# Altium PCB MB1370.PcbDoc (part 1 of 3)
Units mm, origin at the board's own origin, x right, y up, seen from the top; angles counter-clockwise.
Board outline 166 x 117 mm, 4 copper layers (Top Layer, Signal Layer 1, Signal Layer 2, Bottom Layer), stack 1.614 mm thick; 79 components, 100 nets, 342 pads, 822 vias.
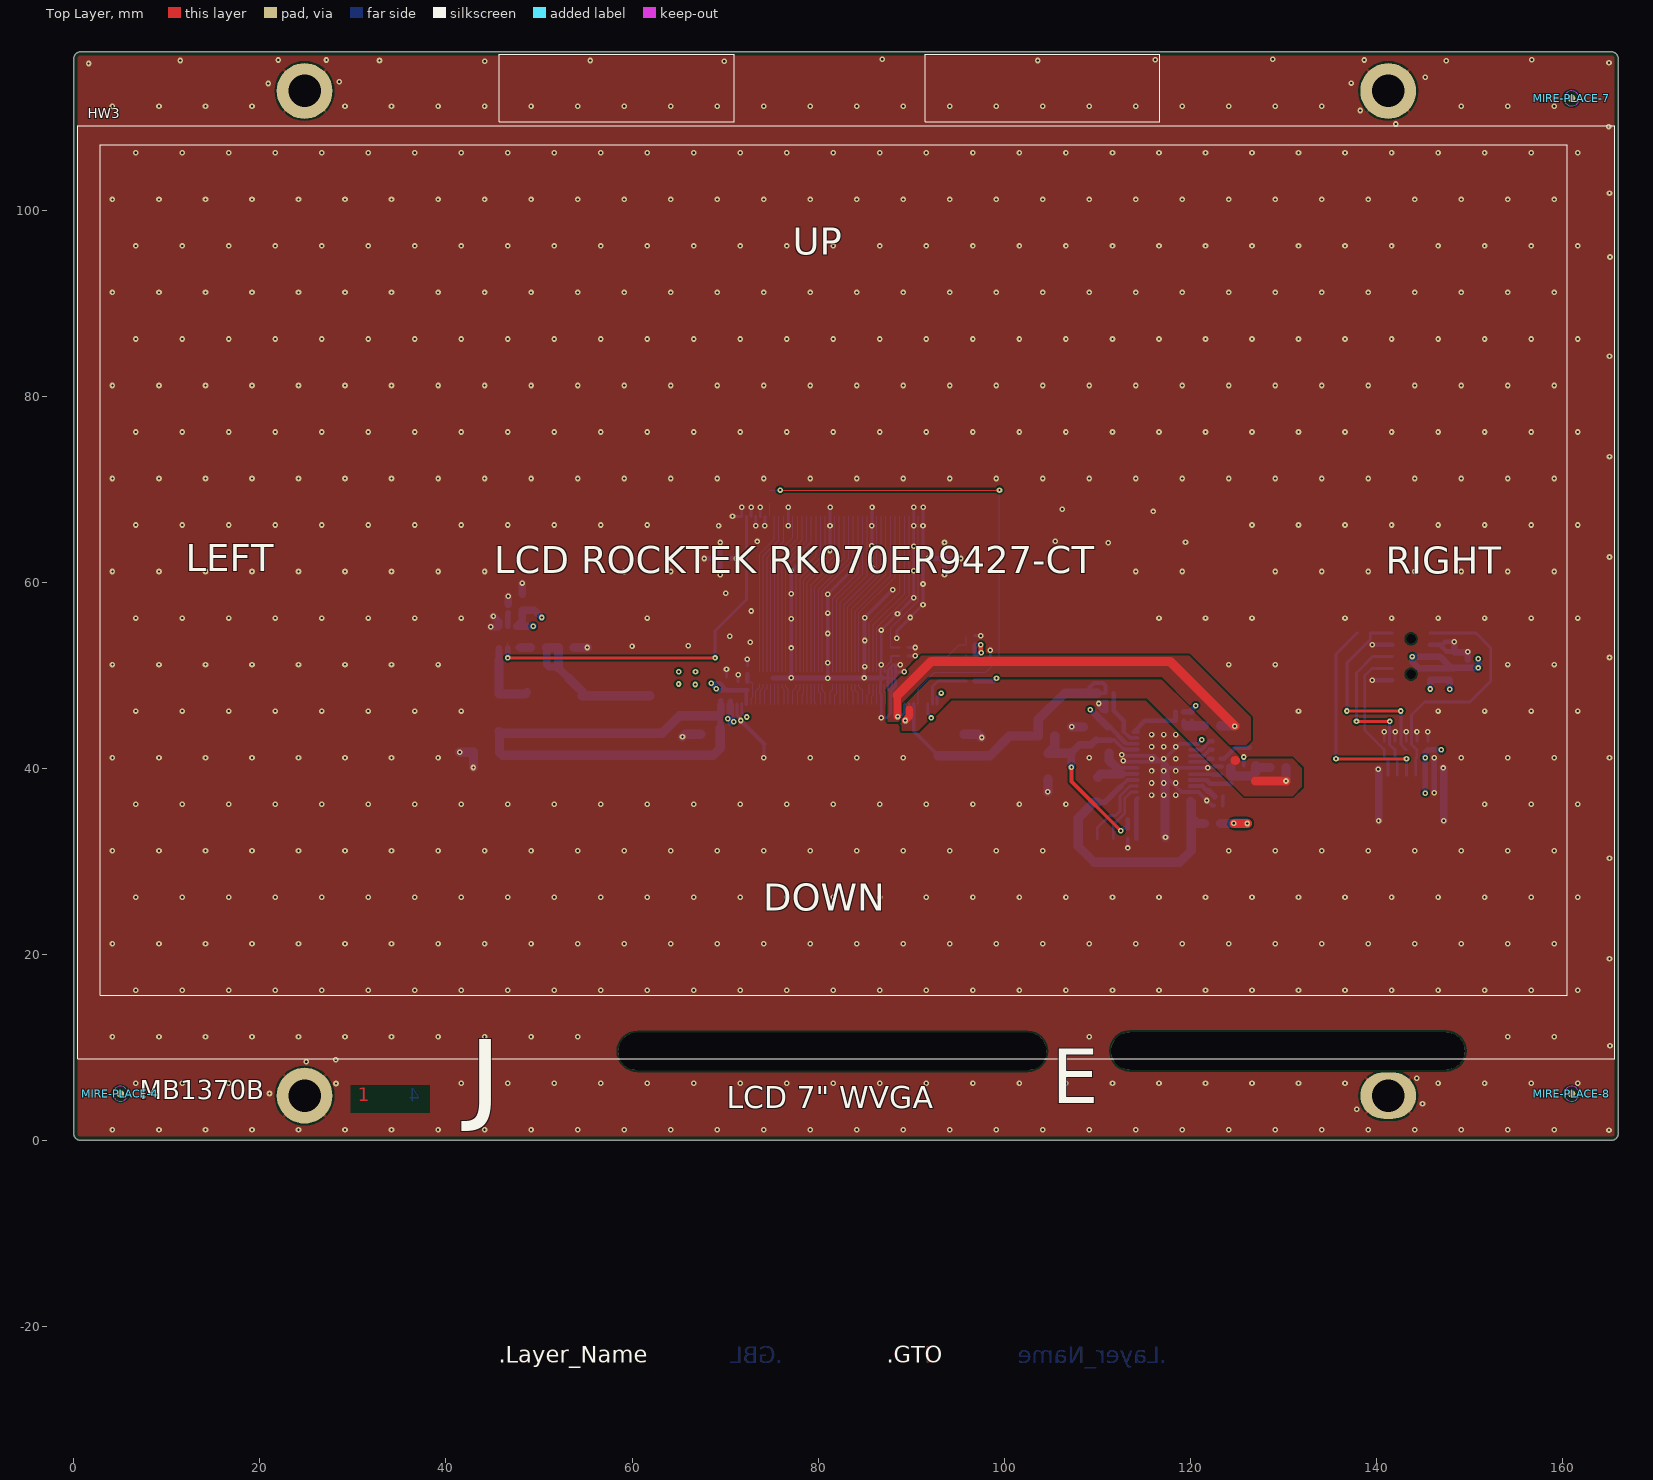
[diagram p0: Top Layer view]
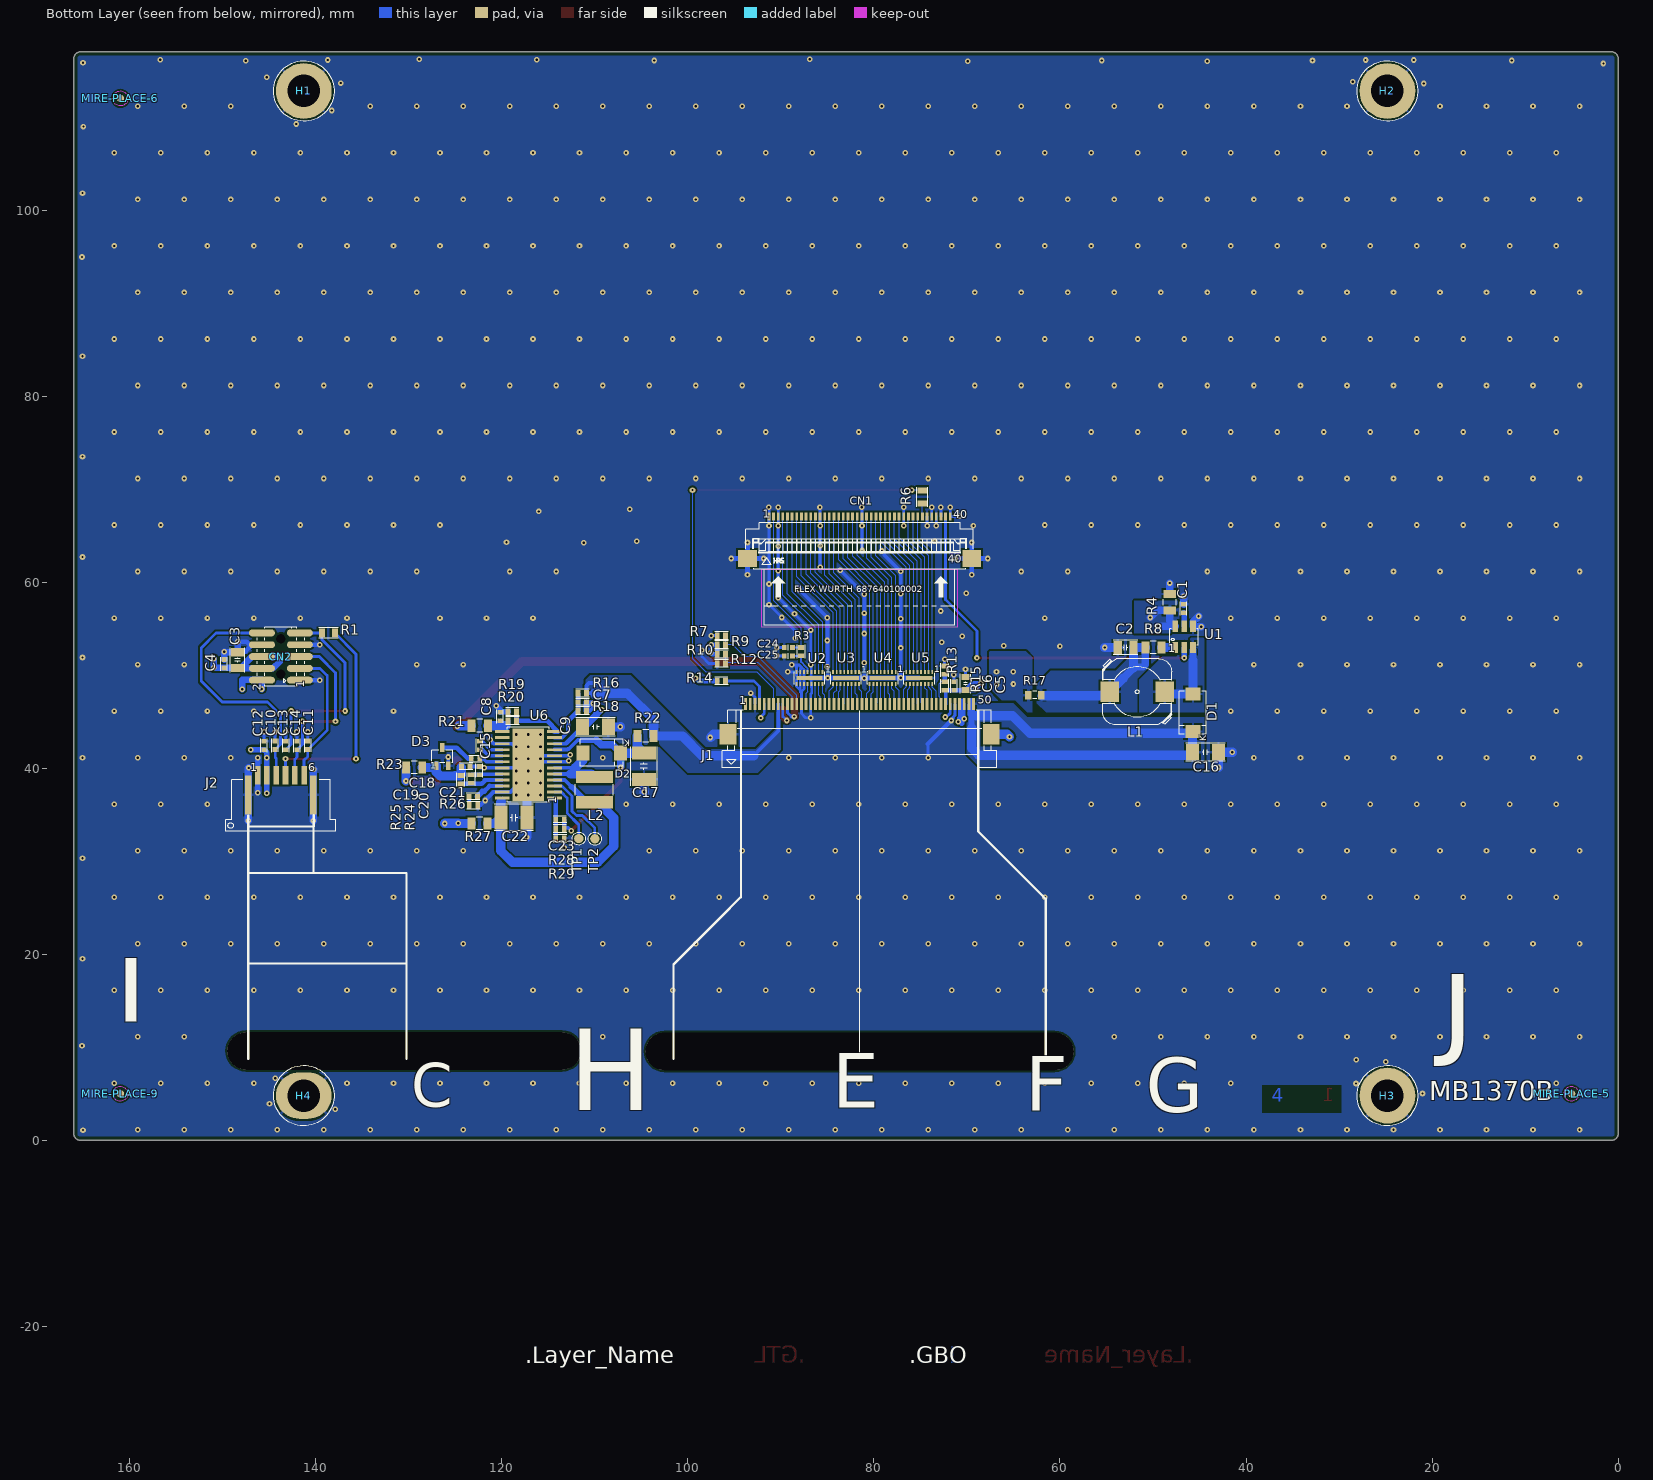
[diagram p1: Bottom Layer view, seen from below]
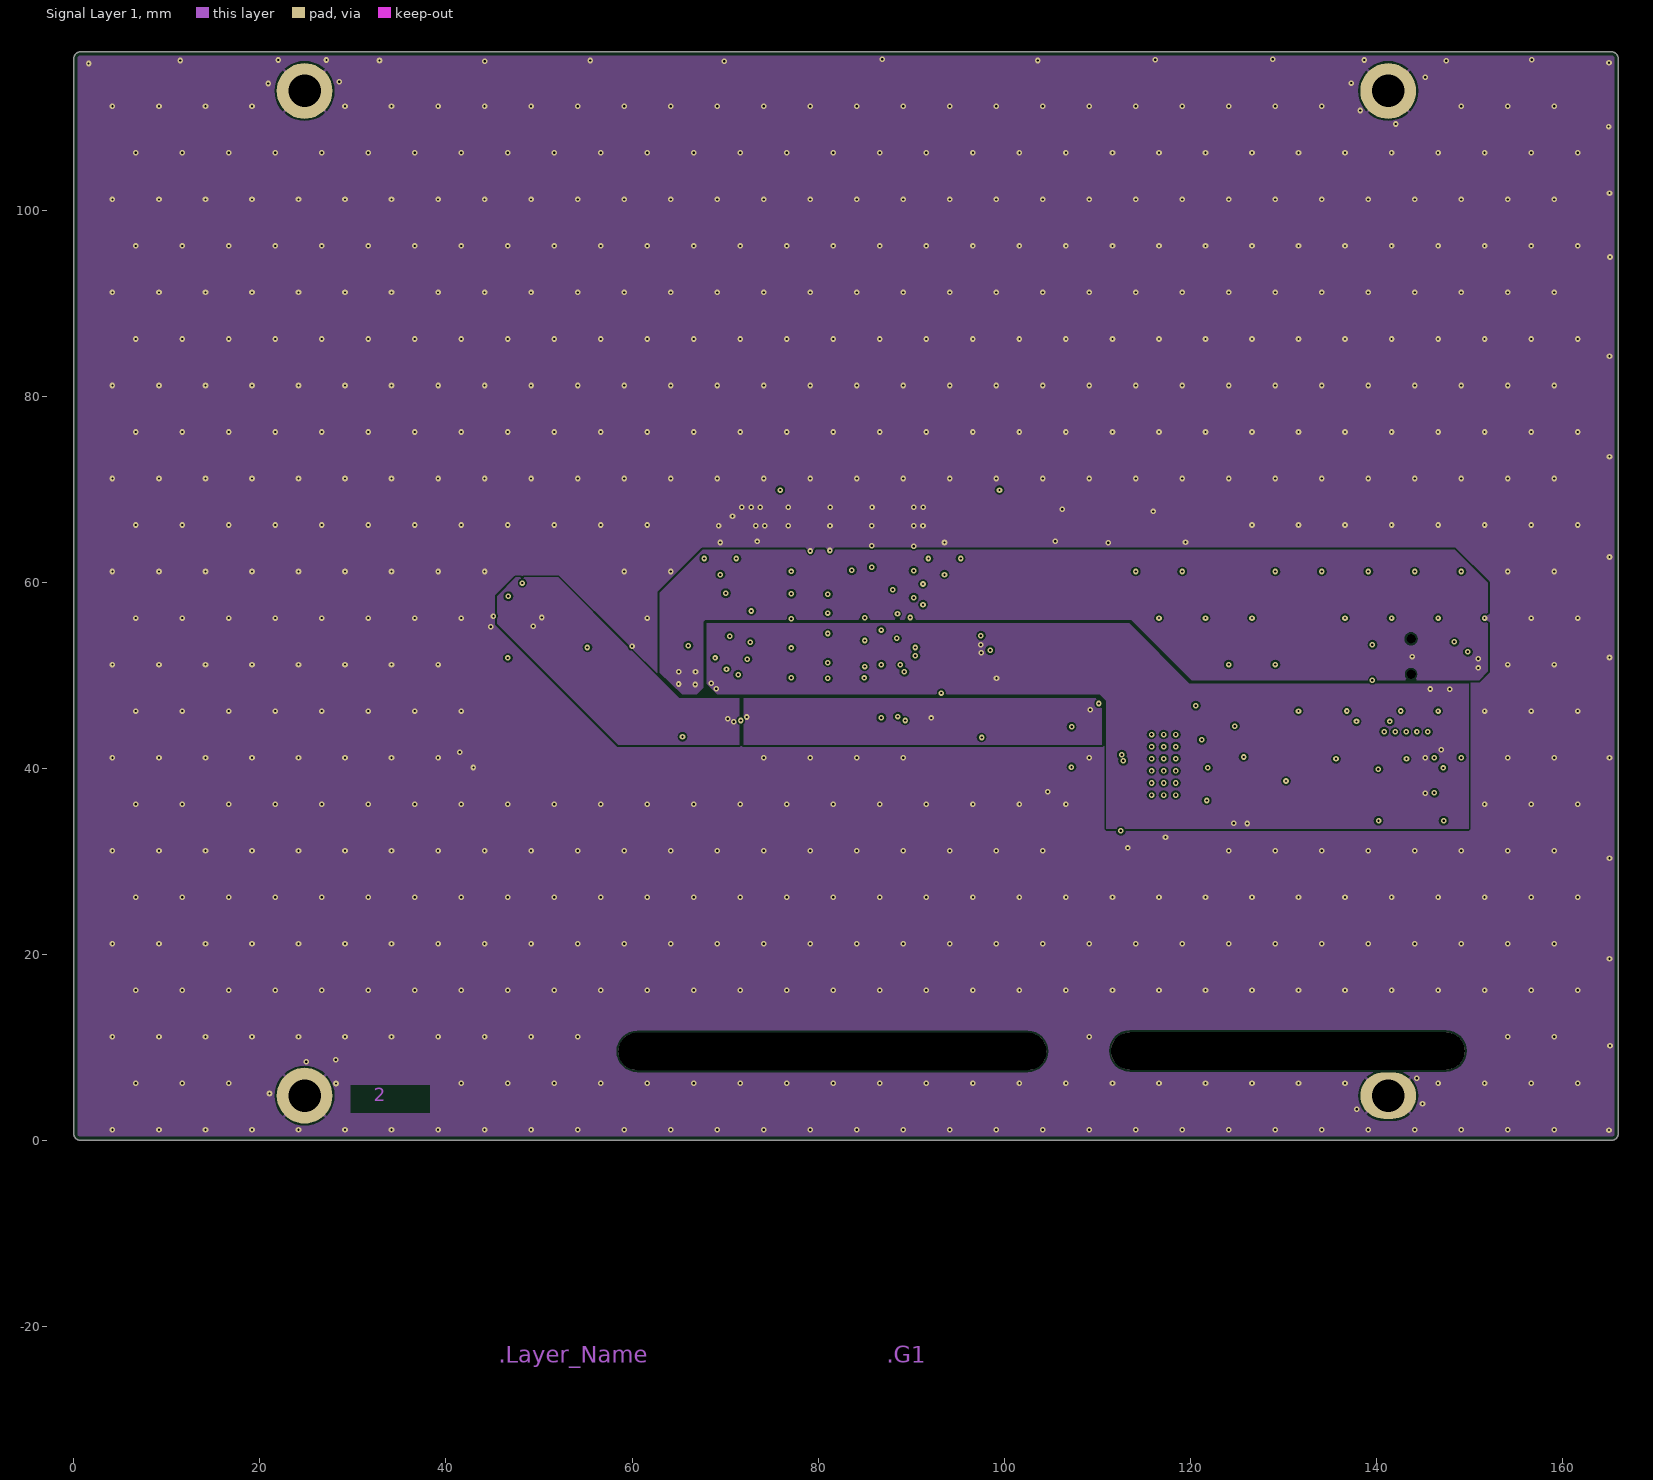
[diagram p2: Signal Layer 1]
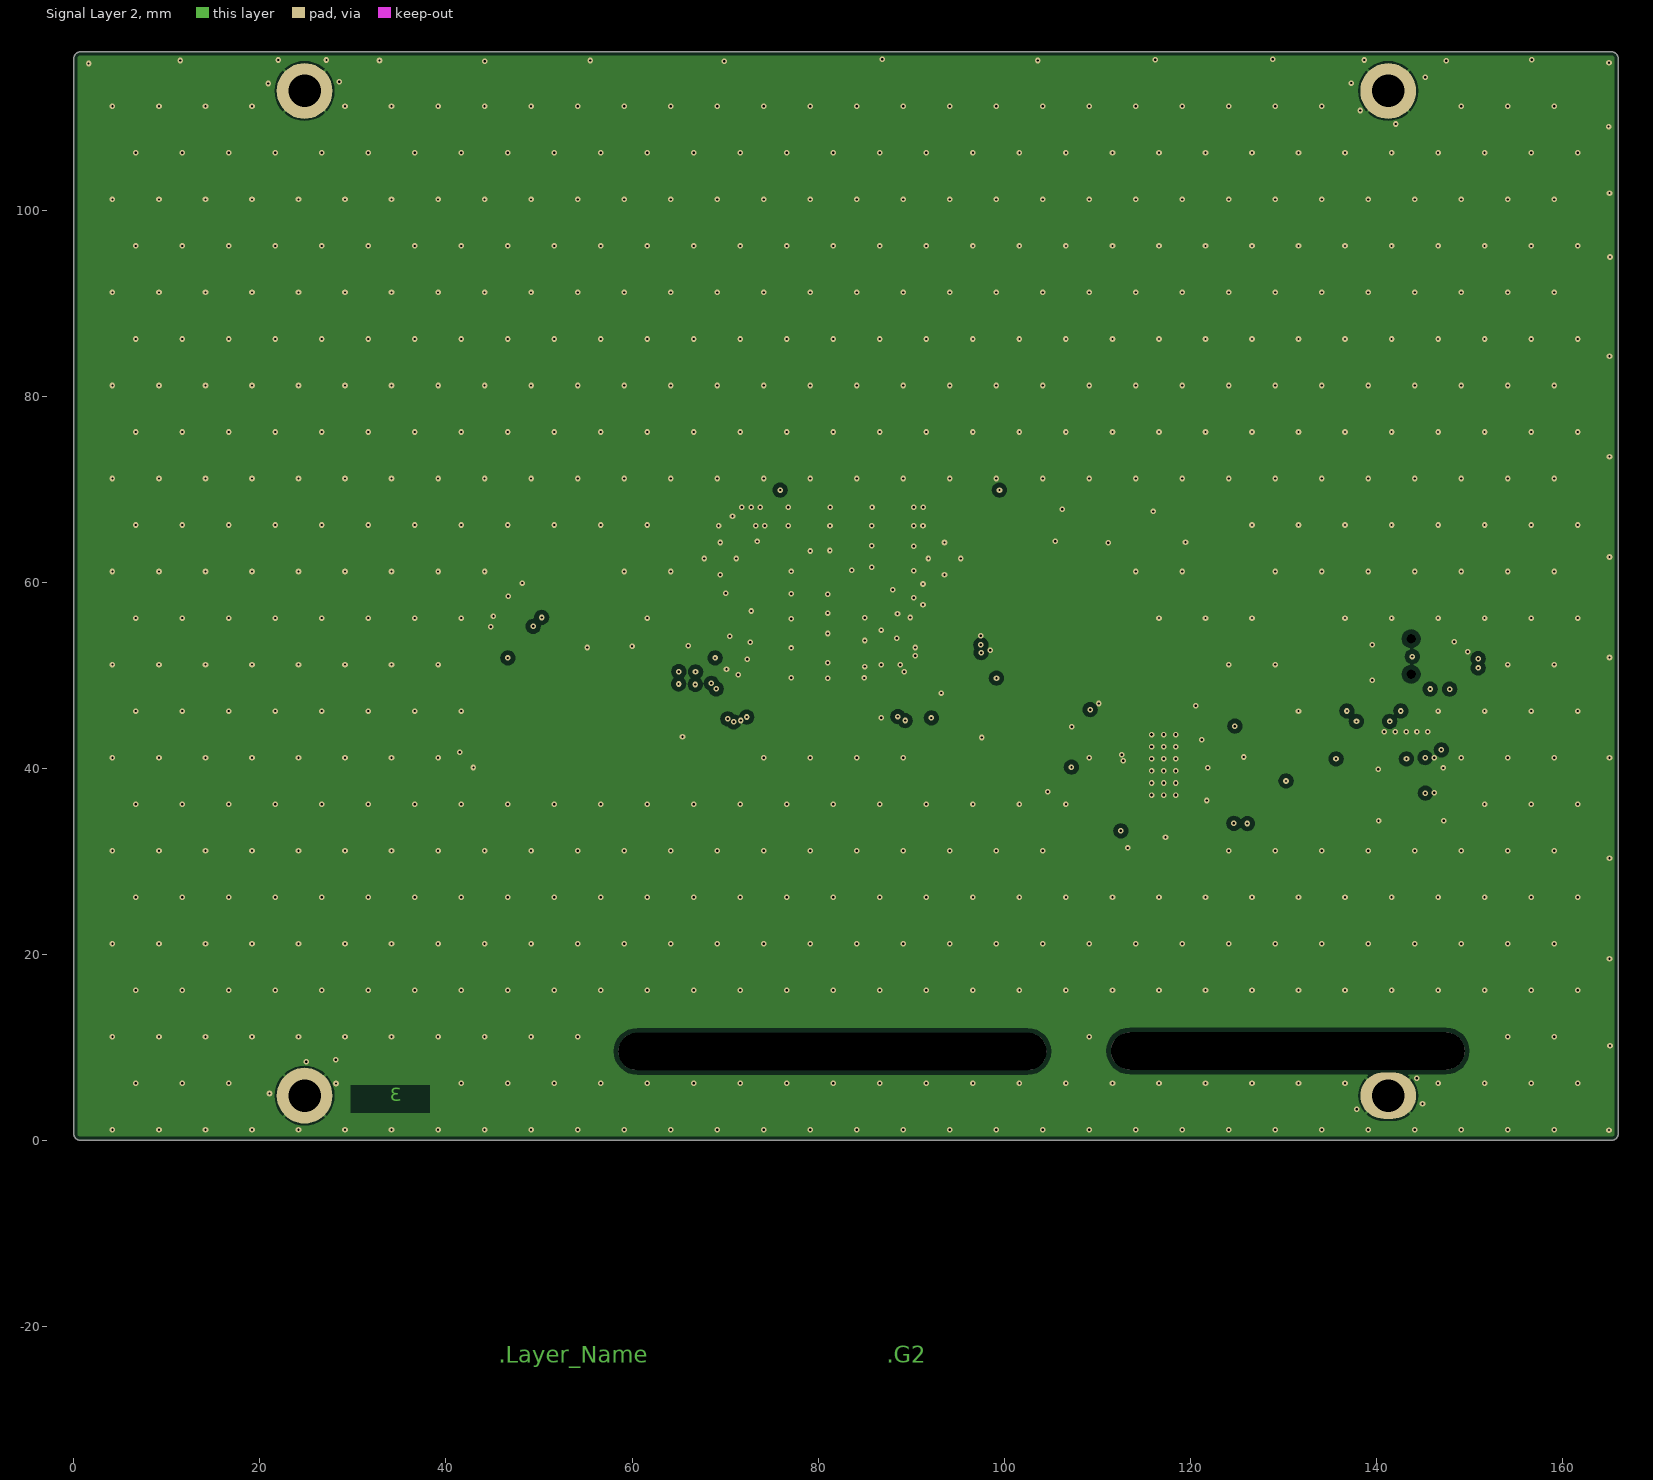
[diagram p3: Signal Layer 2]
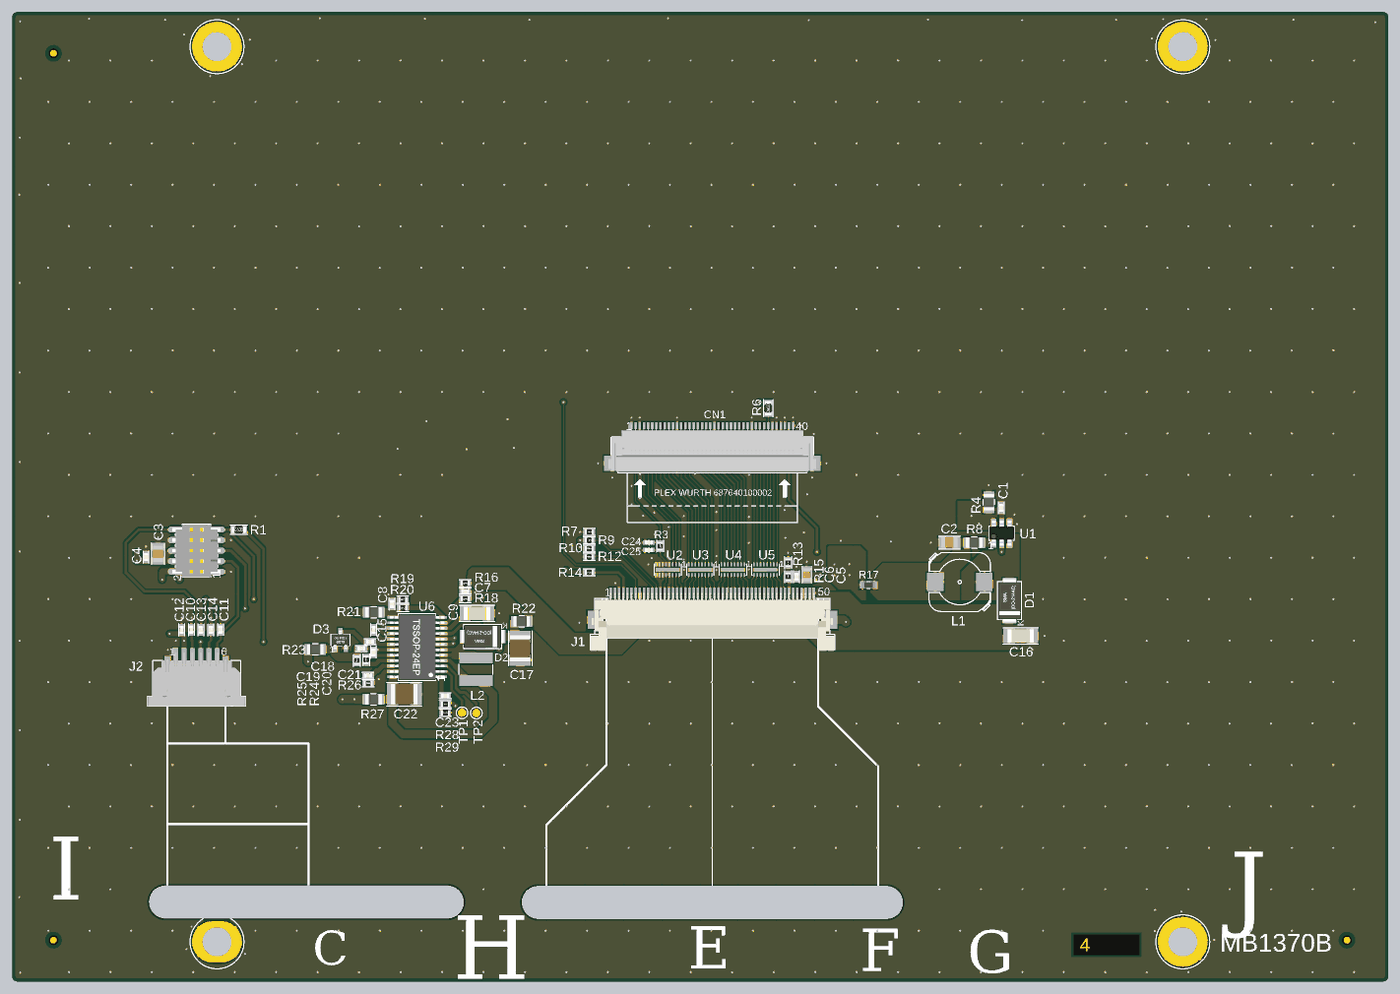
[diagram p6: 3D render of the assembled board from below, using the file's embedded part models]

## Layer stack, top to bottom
Top Solder: solder mask 0.015, Solder Resist, Dk 3.5
Top Layer: signal copper 0.042
Dielectric 1: prepreg 0.106, PP-IT-180A, Dk 4.2
Signal Layer 1: signal copper 0.035
Dielectric 2: core 1.248, FR4, Dk 4.2
Signal Layer 2: signal copper 0.035
Dielectric 3: prepreg 0.106, PP-IT-180A, Dk 4.2
Bottom Layer: signal copper 0.042
Bottom Solder: solder mask 0.015, Solder Resist, Dk 3.5

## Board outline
0,0.69 ccw(c0.691,0.69) 0.691,-0.001 0.69,0 165.31,0 ccw(c165.31,0.691) 166.001,0.691 166,0.69 166,116.31 ccw(c165.309,116.31) 165.309,117.001 165.31,117 0.69,117 ccw(c0.69,116.309) -0.001,116.309 0,116.31

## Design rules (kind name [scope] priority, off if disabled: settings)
BoardOutlineClearance [All] p1: gap=0.4 ignorepadtopadclearanceinfootprint=FALSE except(0: Text-OutlineEdge Text-CavityEdge Text-CutoutEdge Text-SplitBarrior Text-SplitContinuation; 0.2: Track-OutlineEdge Track-CavityEdge Track-CutoutEdge Track-SplitBarrior Track-SplitContinuation)
Clearance Clearance_1 [InNamedPolygon('GND_L03_P034')] p1: gap=0.5 ignorepadtopadclearanceinfootprint=FALSE
Clearance "Stitching GND" [IsStitchingVia and InNet('GND') vs (IsVia and (Not IsStitchingVia)) Or IsPad] p2: gap=0.3 ignorepadtopadclearanceinfootprint=FALSE
Clearance Clearance_2 [InNetClass('POWER')] p3: gap=0.12 ignorepadtopadclearanceinfootprint=TRUE except(0.2: Arc-THPad Arc-Fill Track-THPad Track-Fill SMDPad-SMDPad SMDPad-THPad SMDPad-Fill THPad-THPad THPad-Fill Via-Fill; 0.5: Arc-Poly Track-Poly SMDPad-Poly THPad-Poly Via-Poly Fill-Fill Fill-Poly Fill-Region Fill-Text Fill-Hole Poly-Poly Poly-Region Poly-Text Poly-Hole)
Clearance [All] p4: gap=0.12 ignorepadtopadclearanceinfootprint=TRUE except(0.2: Arc-THPad Arc-Fill Arc-Poly Track-THPad Track-Fill Track-Poly SMDPad-SMDPad SMDPad-THPad SMDPad-Fill SMDPad-Poly THPad-THPad THPad-Fill THPad-Poly Via-Fill Via-Poly Fill-Fill Fill-Poly Poly-Poly)
ComponentClearance [All] p1 off: gap=0.025 collisioncheckmode=3 verticalgap=2540 showdistances=TRUE
DiffPairsRouting DiffPairsRouting_DSI [InDifferentialPairClass('DIFF_DSI')] p1: maxlimit=0.14 minlimit=0.14 mostfreqgap=0.14 toplayer_minwidth=0.12 toplayer_maxwidth=0.12 toplayer_prefwidth=0.12 midlayer1_minwidth=0.12 midlayer1_maxwidth=0.12 midlayer1_prefwidth=0.12 midlayer2_minwidth=0.12 midlayer2_maxwidth=0.12 midlayer2_prefwidth=0.12 bottomlayer_minwidth=0.12 bottomlayer_maxwidth=0.12 bottomlayer_prefwidth=0.12 maxuncoupledlength=50
FanoutControl Fanout_Default [All] p1: bgadir=Out bgaviamode=Closest fanoutstyle=Auto fanoutdirection=Alternating viagrid=0.025 // Fanout_Default (Default Rule)
Height [All] p1 off: minheight=0 maxheight=100 prefheight=0.5
HoleSize [All] p1: absolutevalues=TRUE maxlimit=100 minlimit=0.15 maxpercent=80.000 minpercent=20.000
HoleToHoleClearance [All] p1: gap=0.25 allowstackedmicrovias=TRUE
MatchedLengths [InDifferentialPairClass('DIFF_DSI')] p1: tolerance=5 checknetsindiffpair=FALSE checkdiffpairvsdiffpair=TRUE checkxsignals=TRUE checkothers=TRUE
MinimumSolderMaskSliver [All] p1: minsoldermaskwidth=0
PlaneClearance [All] p1: clearance=0.6
PlaneConnect [All] p1: pad.planeconnectstyle=Relief pad.reliefexpansion=0.508 pad.reliefentries=4 pad.reliefconductorwidth=0.254 pad.reliefairgap=0.254 via.planeconnectstyle=Direct via.reliefexpansion=0.508 via.reliefentries=4 via.reliefconductorwidth=0.254 via.reliefairgap=0.254
PolygonConnect PolygonConnect__DEFAULT [All] p1: thpad.connectstyle=Relief thpad.reliefconductorwidth=0.3 thpad.reliefentries=4 thpad.polygonreliefangle="45 Angle" thpad.airgapwidth=0.2 smdpad.connectstyle=Relief smdpad.reliefconductorwidth=0.3 smdpad.reliefentries=4 smdpad.polygonreliefangle="90 Angle" smdpad.airgapwidth=0.2 via.connectstyle=Direct via.reliefconductorwidth=0.254 via.reliefentries=4 via.polygonreliefangle="45 Angle" via.airgapwidth=0.254
RoutingVias [All] p1: holewidth=0.254 width=0.6 viastyle="Through Hole" minholewidth=0.254 minwidth=0.6 maxholewidth=0.254 maxwidth=0.6
SilkToSilkClearance [All] p1: silktosilkclearance=0
SilkToSolderMaskClearance [IsPad] p1: minsilkscreentomaskgap=0 clearancetoexposedcopper=TRUE
SolderMaskExpansion [All] p1: expansion=0.05
Width Width_ALIMS [InNetClass('ALIMS')] p1: maxlimit=1 minlimit=0.12 preferedwidth=0.3
Width Width_GND [InNetClass('GND')] p2: maxlimit=1 minlimit=0.12 preferedwidth=0.3 minimp=50.000000 maximp=50.000000 favimp=50.000000
Width [All] p3: maxlimit=1 minlimit=0.12 preferedwidth=0.15
15 further rules are at their usual default settings.

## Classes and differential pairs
differential pair class DIFF_DSI: HSSI_CLK HSSI_D0 HSSI_D1
component class U_LCD_PWR: C7 C8 C9 C15 C17 C18 C19 C20 C21 C22 C23 D2 D3 L2 R16 R18 R19 R20 R21 R22 R23 R24 R25 R26 R27 R28 R29 TP1 TP2 U6
component class U_LCD_CTP_FLEX_CONNECTORS: C1 C2 C5 C6 C10 C11 C12 C13 C14 C16 D1 HW3 HW5 J1 J2 L1 R1 R3 R4 R6 R7 R8 R9 R10 R12 R13 R14 R15 U1 U2 U3 U4 U5
component class U_MODULE_TO_MAIN_BOARD_CONNECTOR: C3 C4 R17
net class LCD_B[0..7]: LCD_B0 LCD_B1 LCD_B2 LCD_B3 LCD_B4 LCD_B5 LCD_B6 LCD_B7
net class LCD_G[0..7]: LCD_G0 LCD_G1 LCD_G2 LCD_G3 LCD_G4 LCD_G5 LCD_G6 LCD_G7
net class LCD_R[0..7]: LCD_R0 LCD_R1 LCD_R2 LCD_R3 LCD_R4 LCD_R5 LCD_R6 LCD_R7

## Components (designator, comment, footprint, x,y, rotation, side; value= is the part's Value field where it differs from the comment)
C1 "Capacitor" C0402 46.7,57.164 r270 bottom value=220nF
C2 "Capacitor" C0805 52.95,52.964 r180 bottom value=4.7uF
C3 "Capacitor" C0805 148.4,51.625 r270 bottom value=10uF
C4 "Capacitor" C0402 149.85,51.225 r90 bottom value=100nF
C5 "Capacitor" C0603 70.15,49.089 r270 bottom value=4.7uF
C6 "Capacitor" C0402 71.4,48.839 r270 bottom value=100nF
C7 "Capacitor" C0402 111.35,47.109 r0 bottom value=1nF
C8 "Capacitor" C0402 120.175,45.559 r270 bottom value=220nF
C9 "Capacitor" C1206_H1P15 109.925,44.434 r0 bottom value=1uF
C10 "Capacitor" C0402 144.375,42.46 r270 bottom value=1nF
C11 "Capacitor" C0402 140.85,42.46 r270 bottom value=1nF
C12 "Capacitor" C0402 145.55,42.435 r270 bottom value=1nF
C13 "Capacitor" C0402 143.225,42.435 r270 bottom value=1nF
C14 "Capacitor" C0402 142.025,42.435 r270 bottom value=1nF
C15 "Capacitor" C0402 122.4,42.434 r270 bottom value=220nF
C16 "Capacitor" C1206_H1P15 44.35,41.714 r0 bottom value=1uF
C17 "Capacitor" C1210 104.725,40.209 r90 bottom value=22uF
C18 "Capacitor" C0402 122.825,41.009 r0 bottom value=220nF
C19 "Capacitor" C0402 123.875,40.175 r0 bottom value=220nF
C20 "Capacitor" C0402 122.425,39.734 r270 bottom value=22nF
C21 "Capacitor" C0402 123.075,36.959 r0 bottom value=1nF
C22 "Capacitor" C1210 118.7,34.684 r0 bottom value=22uF
C23 "Capacitor" C0402 113.75,34.484 r180 bottom value=22pF
C24 "Capacitor" C0402 89.2,52.975 r180 bottom value=10pF
C25 "Capacitor" C0402 89.2,52.075 r180 bottom value=10pF
CN1 "FH52E-40S-0.5SH" CON_HRS_FH52E-40S-05SH 81.54,64.8 r180 bottom locked value=FH52E-40S-05SH
CN2 "Header 5x2 Generic" CON_SAMTEC_FTSH-105-01-L-DV-K 143.75,52 r90 bottom value=FTSH-105-01-L-DV-K
D1 "SCHOTTKY_1A_2K" DIO_SMA_1A_2K 45.7,45.964 r90 bottom value=STPS1L40AY
D2 "SCHOTTKY_1A_2K" DIO_SMA_1A_2K 109.25,41.634 r0 bottom value=STPS1L40AY
D3 "DIODE_3P_DUAL_SERIES" DIO_SOT323 126.4,41.234 r180 bottom value=BAT54SWFILM
H1 "POSITION HOLE" PTH_M1261-3005-N_3P5X6_M3_H14#1 141.282,112.8 r0 bottom locked
H2 "POSITION HOLE" PTH_M1261-3005-N_3P5X6_M3_H14#1 24.798,112.8 r0 bottom locked
H3 "POSITION HOLE" PTH_M1261-3005-N_3P5X6_M3_H14#1 24.798,4.8 r0 bottom locked
H4 "POSITION HOLE" PTH_M1261-3005-N_3P5X6_M3_H14#2 141.282,4.8 r0 bottom locked
HW3 "LCD_RK070ER9427L" LCD_DRAWING_ROCKTEK_RK070ER9427-CT 81.7,61.3 r0 top locked value=RK070ER9427-CT
J1 "CONN_FH12S-50S-05SH" CON_HRS_FH12A-50S-05SH 81.54,46.889 r0 bottom locked value=FH12A-50S-0.5SH
J2 "CONN_FH12S-6S-05SH" CON_FCI_SFW6R-1STE9LF 143.75,38.735 r180 bottom value=SFW6R-1STE9LF
L1 "INDUCTOR_POWER" IND_TDK_CLF7045T-100M-D 51.7,48.214 r0 bottom value="10uH 2.7A"
L2 "INDUCTOR_POWER" IND_TDK_VLS4012ET-4R7M 110.05,37.684 r90 bottom value="4.7uH 1.32A"
MIRE-PLACE-4 "MIRE-PLACE-3" MIRE_PLACE_SMD_0P8MM 5,5 r0 top
MIRE-PLACE-5 "MIRE-PLACE-3" MIRE_PLACE_SMD_0P8MM 5,5 r180 bottom
MIRE-PLACE-6 "MIRE-PLACE-3" MIRE_PLACE_SMD_0P8MM 161,112 r180 bottom
MIRE-PLACE-7 "MIRE-PLACE-3" MIRE_PLACE_SMD_0P8MM 161,112 r0 top
MIRE-PLACE-8 "MIRE-PLACE-3" MIRE_PLACE_SMD_0P8MM 161,5 r0 top
MIRE-PLACE-9 "MIRE-PLACE-3" MIRE_PLACE_SMD_0P8MM 161,5 r180 bottom
R1 "Resistor" R0603 138.65,54.525 r180 bottom value=0R
R3 "Resistor" R0402 87.825,52.525 r270 bottom value=0R
R4 "Resistor" R0805 48.2,57.839 r270 bottom value=1R
R6 "Resistor" R0603 74.8,69.175 r90 bottom value=0R
R7 "Resistor" R0402 96.4,54.25 r0 bottom value=10K
R8 "Resistor" R0805 49.95,52.964 r180 bottom value=0R_0805
R9 "Resistor" R0402 96.4,53.25 r0 bottom value=10K
R10 "Resistor" R0402 96.4,52.25 r0 bottom value=10K
R12 "Resistor" R0402 96.4,51.25 r0 bottom value=10K
R13 "Resistor" R0402 72.4,50.539 r270 bottom value=10K
R14 "Resistor" R0402 96.4,49.375 r180 bottom value=10K
R15 "Resistor" R0402 72.4,48.839 r270 bottom value=10K
R16 "Resistor" R0402 111.35,48.059 r0 bottom value=750K
R17 "Inductor" IND_0603_H0P8 62.7,47.85 r180 bottom value="600R @ 100MHz"
R18 "Resistor" R0402 111.35,46.159 r0 bottom value=402K
R19 "Resistor" R0402 118.875,46.084 r180 bottom value=82K
R20 "Resistor" R0402 118.875,45.084 r0 bottom value=1M
R21 "Resistor" R0805 122.375,44.559 r0 bottom value=0R_0805
R22 "Resistor" R0805 104.55,43.459 r180 bottom value=0R_0805
R23 "Resistor" R0805 129.425,40.084 r180 bottom value=0R_0805
R24 "Resistor" R0402 123.3,38.834 r90 bottom value=130K
R25 "Resistor" R0402 124.425,38.759 r270 bottom value=750K
R26 "Resistor" R0402 123.05,35.989 r0 bottom value=15K
R27 "Resistor" R0805 122.4,34.059 r180 bottom value=0R_0805
R28 "Resistor" R0402 113.75,33.484 r180 bottom value=130K
R29 "Resistor" R0402 113.75,32.434 r0 bottom value=16K
TP1 "Test Point" TP_SMD_1MM 111.725,32.434 r90 bottom
TP2 "Test Point" TP_SMD_1MM 110,32.409 r90 bottom
U1 "TPS61165" MOS_SOT23-6L 46.65,54.114 r180 bottom
U2 "FIL_EMIF_ESD_8L" ESD_UQFN16L-EPAD_3P3X1P35_P040 86.925,49.699 r0 bottom value=EMIF08-LCD04M16
U3 "FIL_EMIF_ESD_8L" ESD_UQFN16L-EPAD_3P3X1P35_P040 82.992,49.699 r0 bottom value=EMIF08-LCD04M16
U4 "FIL_EMIF_ESD_8L" ESD_UQFN16L-EPAD_3P3X1P35_P040 79.058,49.699 r0 bottom value=EMIF08-LCD04M16
U5 "FIL_EMIF_ESD_8L" ESD_UQFN16L-EPAD_3P3X1P35_P040 75.125,49.699 r0 bottom value=EMIF08-LCD04M16
U6 "TPS65100" ICC_HTSSOP24-EPAD_7P8X4P4_P065 117.15,40.359 r90 bottom

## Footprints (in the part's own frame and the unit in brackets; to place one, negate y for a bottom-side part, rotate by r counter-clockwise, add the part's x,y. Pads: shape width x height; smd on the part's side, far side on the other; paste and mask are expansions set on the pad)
C0402 [mm]
  rect 0.51x0.56 smd mask+0.05: 1(-0.45,0) 2(0.45,0)
  silkscreen extent -0.72,-0.35 0.72,0.35, body extent -0.5,-0.3 0.5,0.3, height 0.4
C0603 [mm]
  rect 0.64x0.89 smd mask+0.05: 1(-0.7,0) 2(0.7,0)
  silkscreen extent -1.05,-0.55 1.02,0.55, body extent -0.9,-0.5 0.9,0.5, height 1.4
C0805 [mm]
  rect 0.9x1.4 smd mask+0.05: 1(-0.85,0) 2(0.85,0)
  silkscreen extent -1.3,-0.77 1.3,0.77, body extent -1.1,-0.7 1.1,0.7, height 1.35
C1206_H1P15 [mm]
  rect 1.4x1.78 smd mask+0.05: 1(-1.4,0) 2(1.4,0)
  silkscreen extent -2.12,-0.97 2.15,0.97, body extent -1.7,-0.9 1.7,0.9, height 1.35
C1210 [mm]
  rect 1.4x2.6 smd mask+0.05: 1(-1.4,0) 2(1.4,0)
  silkscreen extent -2.1,-1.43 2.1,1.43, body extent -1.75,-1.35 1.75,1.35, height 2.5
CON_FCI_SFW6R-1STE9LF [mm] "MCD-01363"
  rect 0.6x2 smd mask+0.05: 1(-2.5,0.5) 2(-1.5,0.5) 3(-0.5,0.5) 4(0.5,0.5) 5(1.5,0.5) 6(2.5,0.5)
  rect 0.7x4.2 smd mask+0.05: MT1(-3.5,-1.6) MT2(3.5,-1.6)
  silkscreen extent -5.9,-5.5 5.9,0, body extent -5.9,-5.5 5.9,1, height 2.7
CON_HRS_FH12A-50S-05SH [mm]
  rect 0.3x1.3 smd mask+0.05: 1(12.25,0) 2(11.75,0) 3(11.25,0) 4(10.75,0) 5(10.25,0) 6(9.75,0) 7(9.25,0) 8(8.75,0) 9(8.25,0) 10(7.75,0) 11(7.25,0) 12(6.75,0) 13(6.25,0) 14(5.75,0) 15(5.25,0) 16(4.75,0) 17(4.25,0) 18(3.75,0) 19(3.25,0) 20(2.75,0) 21(2.25,0) 22(1.75,0) 23(1.25,0) 24(0.75,0) 25(0.25,0) 26(-0.25,0) 27(-0.75,0) 28(-1.25,0) 29(-1.75,0) 30(-2.25,0) 31(-2.75,0) 32(-3.25,0) 33(-3.75,0) 34(-4.25,0) 35(-4.75,0) 36(-5.25,0) 37(-5.75,0) 38(-6.25,0) 39(-6.75,0) 40(-7.25,0) 41(-7.75,0) 42(-8.25,0) 43(-8.75,0) 44(-9.25,0) 45(-9.75,0) 46(-10.25,0) 47(-10.75,0) 48(-11.25,0) 49(-11.75,0) 50(-12.25,0)
  rect 1.8x2.2 smd mask+0.05: MT1(-14.15,3.25) MT2(14.15,3.25)
  silkscreen extent -14.75,0.65 14.75,6.85, body extent -14.75,0 14.75,7, height 3.6
CON_HRS_FH52E-40S-05SH [mm] "MCD-01992"
  rect 0.3x0.85 smd mask+0.05: 1(-9.75,2.263) 2(-9.25,2.263) 3(-8.75,2.263) 4(-8.25,2.263) 5(-7.75,2.263) 6(-7.25,2.263) 7(-6.75,2.263) 8(-6.25,2.263) 9(-5.75,2.263) 10(-5.25,2.263) 11(-4.75,2.263) 12(-4.25,2.263) 13(-3.75,2.263) 14(-3.25,2.263) 15(-2.75,2.263) 16(-2.25,2.263) 17(-1.75,2.263) 18(-1.25,2.263) 19(-0.75,2.263) 20(-0.25,2.263) 21(0.25,2.263) 22(0.75,2.263) 23(1.25,2.263) 24(1.75,2.263) 25(2.25,2.263) 26(2.75,2.263) 27(3.25,2.263) 28(3.75,2.263) 29(4.25,2.263) 30(4.75,2.263) 31(5.25,2.263) 32(5.75,2.263) 33(6.25,2.263) 34(6.75,2.263) 35(7.25,2.263) 36(7.75,2.263) 37(8.25,2.263) 38(8.75,2.263) 39(9.25,2.263) 40(9.75,2.263)
  rect 2x1.8 smd mask+0.05: MT1(-12.05,-2.262) MT2(12.05,-2.262)
  Top Layer keep-out region: -10.5,-3.412 10.5,-3.412 10.5,-9.662 -10.5,-9.662
  silkscreen extent -12.23,-9.41 12.22,1.59, body extent -12.65,-9.41 12.65,2.4, height 4.1
CON_SAMTEC_FTSH-105-01-L-DV-K [mm]
  oval 0.74x2.79 smd mask+0.05: 1(-2.54,-2.035) 2(-2.54,2.035) 3(-1.27,-2.035) 4(-1.27,2.035) 5(0,-2.035) 6(0,2.035) 7(1.27,-2.035) 8(1.27,2.035) 9(2.54,-2.035) 10(2.54,2.035)
  round 0 hole 1 unplated paste-10 mask+0.05: NPTH1(-1.905,0) NPTH2(1.905,0)
  silkscreen extent -3.17,-2.54 3.17,2.54, body extent -3.17,-2.92 3.18,2.92, height 6.12
DIO_SMA_1A_2K [mm]
  rect 1.4x1.64 smd mask+0.05: 1(2.015,0) 2(-2.015,0)
  silkscreen extent -2.3,-1.45 2.3,1.45, body extent -2.75,-1.45 2.75,1.45, height 2.7
DIO_SOT323 [mm]
  rect 0.5x0.95 smd mask+0.05: 1(-0.65,-0.975) 2(0.65,-0.975) 3(0,0.975)
  silkscreen extent -1.15,-0.67 1.15,0.67, body extent -1.15,-1.12 1.15,1.12, height 1.1
ESD_UQFN16L-EPAD_3P3X1P35_P040 [mm]
  rect 0.2x0.45 smd mask+0.05: 1(-1.4,-0.65) 2(-1,-0.65) 3(-0.6,-0.65) 4(-0.2,-0.65) 5(0.2,-0.65) 6(0.6,-0.65) 7(1,-0.65) 8(1.4,-0.65) 9(1.4,0.65) 10(1,0.65) 11(0.6,0.65) 12(0.2,0.65) 13(-0.2,0.65) 14(-0.6,0.65) 15(-1,0.65) 16(-1.4,0.65)
  rect 2.8x0.4 smd mask+0.05: EP(0,0)
  silkscreen extent -1.65,-0.67 1.65,0.67, body extent -1.65,-0.67 1.65,0.67, height 0.6
ICC_HTSSOP24-EPAD_7P8X4P4_P065 [mm]
  rect 0.3x1.6 smd mask+0.05: 1(-3.575,-2.8) 2(-2.925,-2.8) 3(-2.275,-2.8) 4(-1.625,-2.8) 5(-0.975,-2.8) 6(-0.325,-2.8) 7(0.325,-2.8) 8(0.975,-2.8) 9(1.625,-2.8) 10(2.275,-2.8) 11(2.925,-2.8) 12(3.575,-2.8) 13(3.575,2.8) 14(2.925,2.8) 15(2.275,2.8) 16(1.625,2.8) 17(0.975,2.8) 18(0.325,2.8) 19(-0.325,2.8) 20(-0.975,2.8) 21(-1.625,2.8) 22(-2.275,2.8) 23(-2.925,2.8) 24(-3.575,2.8)
  rect 7.8x3.4 smd paste-10 mask-10: EP(0,0)
  silkscreen extent -4.03,-2.25 4.03,2.25, body extent -3.95,-3.28 3.95,3.28, height 1.25
IND_0603_H0P8 [mm]
  rect 0.7x0.9 smd mask+0.05: 1(-0.7,0) 2(0.7,0)
  silkscreen extent -0.2,-0.4 0.2,0.4, body extent -0.8,-0.4 0.8,0.4, height 0.8
IND_TDK_CLF7045T-100M-D [mm]
  rect 2x2.2 smd mask+0.05: 1(-2.95,0) 2(2.95,0)
  silkscreen extent -3.7,-3.55 3.7,3.55, body extent -3.83,-3.55 3.82,3.55, height 4.8
IND_TDK_VLS4012ET-4R7M [mm]
  rect 1.3x4 smd mask+0.05: 1(-1.35,0) 2(1.35,0)
  silkscreen extent -0.6,-2.05 0.6,2.05, body extent -2.05,-2.05 2.05,2.05, height 1.2
LCD_DRAWING_ROCKTEK_RK070ER9427-CT [mm] "MCD-00604"
  silkscreen extent -81.26,-52.56 83.94,47.74, body extent -81.26,-52.56 83.94,47.74, height 7.9
MIRE_PLACE_SMD_0P8MM [mm]
  round 0.8 smd paste-10 mask+0.2: 1(0,0)
  Top Layer keep-out circle w0.01: c0,0 r0.804
MOS_SOT23-6L [mm]
  rect 0.6x1.2 smd mask+0.05: 1(-0.95,-1.15) 2(0,-1.15) 3(0.95,-1.15) 4(0.95,1.15) 5(0,1.15) 6(-0.95,1.15)
  silkscreen extent -1.53,-0.87 1.53,0.87, body extent -1.52,-1.5 1.52,1.5, height 1.3
PTH_M1261-3005-N_3P5X6_M3_H14#1 [mm]
  round 6 hole 3.5 mask+0.05: 1(0,0)
  silkscreen extent -3.25,-3.25 3.25,3.25, body extent -2.5,-2.5 2.5,2.5, height 14
PTH_M1261-3005-N_3P5X6_M3_H14#2 [mm]
  oval 6x5 hole 3.5 mask+0.05: 1(0,0)
  silkscreen extent -3.25,-3.25 3.25,3.25, body extent -2.5,-2.5 2.5,2.5, height 14
R0402 [mm]
  rect 0.51x0.7 smd mask+0.05: 1(-0.45,0) 2(0.45,0)
  silkscreen extent -0.72,-0.43 0.72,0.43, body extent -0.52,-0.3 0.52,0.3, height 0.4
R0603 [mm]
  rect 0.64x1 smd mask+0.05: 1(-0.7,0) 2(0.7,0)
  silkscreen extent -1.05,-0.58 1.05,0.58, body extent -0.9,-0.5 0.9,0.5, height 0.56
R0805 [mm]
  rect 0.85x1.3 smd mask+0.05: 1(-0.875,0) 2(0.875,0)
  silkscreen extent -0.33,-0.67 0.33,0.67, body extent -1.05,-0.68 1.05,0.68, height 0.65
TP_SMD_1MM [mm]
  round 1 smd paste-10 mask+0.05: 1(0,0)
  silkscreen extent -0.7,-0.7 0.7,0.7

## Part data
C1 C8 C15 C18 C19: library part MCD-00602, "Capacitor, MLCC, 220nF, 16V, 0402, X7R, 10%, T=0,5mm", Manufacturer=MURATA, Manufacturer_Part_Number=GRM155R71C223KA01J, Package=C0402
C2: library part MCD-01974, "Capacitor, MLCC, 4.7uF, 16V, 0805, X5R, 10%, T=1,25mm", Alternate_Manufacturer=KEMET, Alternate_Manufacturer_Part_Number=C0805C475K4PACTU, Manufacturer="TAIYO YUDEN", Manufacturer_Part_Number=EMK212ABJ475KG-T, Package=C0805
C3: library part MCD-00014, "Capacitor, MLCC, 10uF, 25V, X5R, 10%, 0805, T=0,85mm", Manufacturer=YAGEO, Manufacturer_Part_Number=CC0805KRX5R8BB106, Package=C0805
C4 C6: library part MCD-00006, "Capacitor, MLCC, 100nF, 16V, X7R, 10%, 0402, T=0.5mm", Alternate_Manufacturer=MURATA, Alternate_Manufacturer_Part_Number=GCM155R71C104KA55D, Manufacturer=YAGEO, Manufacturer_Part_Number=CC0402KRX7R7BB104, Package=C0402
C5: library part MCD-00009, "Capacitor, MLCC, 4.7uF, 16V, X5R, 10%, 0603, T=0.8mm", Manufacturer=YAGEO, Manufacturer_Part_Number=CC0603KRX5R7BB475, Package=C0603
C7 C10 C11 C12 C13 C14 C21: library part MCD-00198, "Capacitor, MLCC, 1nF, 16V, X7R, 10%, 0402, T=0.5mm", Manufacturer=YAGEO, Manufacturer_Part_Number=CC0402KRX7R7BB102, Package=C0402
C9 C16: library part MCD-01997, "Capacitor, MLCC, 1uF, 50V, 1206, X7R, 10%, T=1mm", Manufacturer=KEMET, Manufacturer_Part_Number=C1206C105K5RACTU, Package=C1206
C17 C22: library part MCD-00614, "Capacitor, MLCC, 22uF, 16V, 1210, X7R, 20%, T=2,5mm, ESR 2mohm@410KHz", Manufacturer=MURATA, Manufacturer_Part_Number=GCM32ER71C226ME19, Package=C1210
C20: library part MCD-00202, "Capacitor, MLCC, 22nF, 16V, X7R, 10%, 0402, T=0.5mm", Manufacturer=YAGEO, Manufacturer_Part_Number=CC0402KRX7R7BB223, Package=C0402
C23: library part MCD-01995, "Capacitor, MLCC, 22pF, 50V, C0G, 5%, 0402, T=0,5mm", Manufacturer=TDK, Manufacturer_Part_Number=C1005NP01H220J050BA, Package=C0402
C24 C25: library part MCD-00015, "Capacitor, MLCC, 10pF, 50V, NPO, 5%, 0402, T=0,5mm", Manufacturer=YAGEO, Manufacturer_Part_Number=CC0402JRNPO9BN100, Package=C0402
CN1: library part MCD-01992, "FFC et FPC connector 0.5MM 40P LNG MTL FITNG SMT VERT MNT", Manufacturer=HIROSE, Manufacturer_Part_Number=FH52E-40S-05SH
CN2: library part MCD-00610, "Surface mount, vertical male connector. Double row of 5 pins, 1.27mm pitch, 3.05mm lead. Mates with FFSD connector", Alternate_Manufacturer=JIUBABA, Alternate_Manufacturer_Part_Number=P127B-2x05MGF-079-1A, Manufacturer=SAMTEC, Manufacturer_Part_Number=FTSH-105-01-L-DV-K
D1 D2: library part MCD-00606, "Low Drop power Schottky rectifier(1A, 40V, 0.37 V)", Manufacturer=STMICROELECTRONICS, Manufacturer_Part_Number=STPS1L40AY, Package=SMA
D3: library part MCD-00608, "Dual surface mount small signal schotky diode in series", Manufacturer=STMICROELECTRONICS, Manufacturer_Part_Number=BAT54SWFILM
H1 H2 H3 H4: library part MCD-00035, "POSITION HOLE C6D3R5", Manufacturer=n/a
HW3: library part MCD-00604, "Display (TFT LCD) - 7-inch LCD Module 800x480 (RGB 24-bit) with integrated capacitive touch panel", Manufacturer=ROCKTEK, Manufacturer_Part_Number=RK070ER9427-CT
J1: library part MCD-01042, "50-pin 05mm Pitch connector for FPC/FFC top contact version", Manufacturer=HIROSE, Manufacturer_Part_Number=FH12A-50S-0.5SH
J2: library part MCD-01363, "6-pin 1mm Pitch SMT connector for FPC/FFC lower contact type", Manufacturer=FCI, Manufacturer_Part_Number=SFW6R-1STE9LF
L1: library part MCD-00615, "Magnetic shield type wound inductor for power circuits 10uH 38mOhms 2.7A 20%", Manufacturer=TDK, Manufacturer_Part_Number=CLF7045T-100M-D
L2: library part MCD-01996, "Surface mount Wound Magnetically shielded Power inductor. 4.7uH +/-20%; DCres:95mohm; 1.32A(-30% from initial value); 1.57A(+40°C temperature rise)", Manufacturer="TAIYO YUDEN", Manufacturer_Part_Number=NRS4012T4R7MDGJ, Package=4012
R1 R6: library part MCD-00056, "Resistor,0R,0603,5%,1/10W", Manufacturer=YAGEO, Manufacturer_Part_Number=RC0603JR-070RL, Package=R0603
R3: library part MCD-00052, "Resistor,0R,0402,5%,1/16W", Manufacturer=YAGEO, Manufacturer_Part_Number=RC0402JR-070RL, Package=R0402
R4: library part MCD-00323, "Resistor, 1R, 0805, 1%, 1/8W", Manufacturer=YAGEO, Manufacturer_Part_Number=RC0805FR-071RL, Package=R0805
R7 R9 R10 R12 R13 R14 R15: library part MCD-00053, "Resistor,10K,0402,1%,1/16W", Manufacturer=YAGEO, Manufacturer_Part_Number=RC0402FR-0710KL, Package=R0402
R8 R21 R22 R23 R27: library part MCD-00179, "Resistor,0R,0805,5%", Manufacturer=YAGEO, Manufacturer_Part_Number=RC0805JR-070RL, Package=R0805
R16 R25: library part MCD-00523, "Resistor,750K,0402,1%,1/16W", Manufacturer=YAGEO, Manufacturer_Part_Number=RC0402FR-07750KL, Package=R0402
R17: library part MCD-00593, "Ferrite bead, 600R @ 100MHz,  1.3A, 150mOhm, 0603", Manufacturer=MURATA, Manufacturer_Part_Number=BLM18KG601SN1D
R18: library part MCD-00607, "Resistor,402K,0402,1%,1/16W", Manufacturer=YAGEO, Manufacturer_Part_Number=RC0402FR-07402KL, Package=R0402
R19: library part MCD-00531, "Resistor,82K,0402,1%,1/16W", Manufacturer=YAGEO, Manufacturer_Part_Number=RC0402FR-0782KL, Package=R0402
R20: library part MCD-00182, "Resistor,1M,0402,1%,1/16W", Manufacturer=YAGEO, Manufacturer_Part_Number=RC0402FR-071ML, Package=R0402
R24 R28: library part MCD-00385, "Resistor,130K,0402,1%,1/16W", Manufacturer=YAGEO, Manufacturer_Part_Number=RC0402FR-07130KL, Package=R0402
R26: library part MCD-00285, "Resistor,15K,0402,5%,1/16W", Manufacturer=YAGEO, Manufacturer_Part_Number=RC0402JR-0715KL, Package=R0402
R29: library part MCD-00403, "Resistor,16K,0402,1%,1/16W", Manufacturer=YAGEO, Manufacturer_Part_Number=RC0402FR-0716KL, Package=R0402
TP1 TP2: library part MCD-00074, "Test Point 1mm", Manufacturer=n/a
U1: library part MCD-00601, "High-Brightness White LED Driver in SOT-23 Package", Manufacturer="TEXAS INSTRUMENTS"
U2 U3 U4 U5: library part MCD-00599, "8-line L-C EMI filter and ESD protection for LCD application", Manufacturer=STMICROELECTRONICS, Manufacturer_Part_Number=EMIF08-LCD04M16
U6: library part MCD-00613, "Triple-Output LCD Supply With Linear Regulator and VCOM Buffer", Manufacturer="TEXAS INSTRUMENTS", Manufacturer_Part_Number=TPS65100PWP, Package=TSSOP24

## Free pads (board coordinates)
  round 0.508 on Mech16: 1(57.358,-30.85) 1(106.205,-30.85)
  oval 46x4 hole 4 slot 46 at 0 deg unplated mask+0.1: 1(81.54,9.55)
  oval 38x4 hole 4 slot 38 at 0 deg unplated mask+0.1: 1(130.5,9.6)

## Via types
v1: diameter 0.6, hole 0.254, Top Layer to Bottom Layer, tented both sides, 804 vias
v2: diameter 0.6, hole 0.3, Top Layer to Bottom Layer, tented both sides, 18 vias

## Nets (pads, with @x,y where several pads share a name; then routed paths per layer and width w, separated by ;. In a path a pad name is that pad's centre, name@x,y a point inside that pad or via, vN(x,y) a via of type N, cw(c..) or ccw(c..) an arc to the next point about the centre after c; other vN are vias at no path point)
3V3: C5.2 C6.2 C12.2 CN2.2 J1.44 J2.2 R9.2 R10.2 R14.1 R15.2 R27.1 | length 28.9
  Top Layer w0.5: v1(97.5,53.25) 97.5,52.45 v1(97.525,52.425)
  Top Layer w1: v1@124.709,34.05 v1(126.15,34.05)
  Bottom Layer w0.4: J1.44@72.29,46.889 72.29,48.279 R15.2@72.4,48.389
  Bottom Layer w0.5: R15.2@72.4,48.389 C6.2@71.4,48.389 C5.2@70.15,48.389 ; R14.1@96.85,49.375 98.875,49.375 v1(99.175,49.675) ; C5.2@70.15,48.389 69.186,48.389 v1(69.05,48.525) 68.525,49.05 v1(68.525,49.125) 69.414,49.125 C5.2@70.15,48.389 ; R10.2@96.85,52.25 97.35,52.25 v1(97.525,52.425) 97.525,53.225 v1(97.5,53.25) R9.2@96.85,53.25 R10.2@96.85,52.25
  Bottom Layer w0.6: v1(145.275,37.325) 145.25,37.35 J2.2@145.25,39.235 v1(145.25,41.125) 145.25,41.685 C12.2@145.55,41.985 146.99,41.985 v1(147,41.975)
  Bottom Layer w0.7: v1(145.79,48.51) 145.785,48.51 CN2.2@145.785,49.46 145.825,49.5 147.9,49.5 v1(147.9,48.5)
  Bottom Layer w1: R27.1@123.275,34.059 124.684,34.059 v1(124.7,34.075) 126.125,34.075 v1(126.15,34.05)
5V: C2.2 L1.2 R8.1 R17.2 | length 18.1
  Bottom Layer w0.8: R8.1@50.825,52.964 50.825,51.15 51.1,50.875 51.989,50.875 52.1,50.764 53.182,49.682 ; L1.2@54.65,47.8 L1.2@54.65,48.214 ; R17.2@61.911,47.8 R17.2@61.95,47.839
  Bottom Layer w1: R8.1@50.825,52.964 C2.2@52.1,52.964 52.1,50.764 ; 53.182,49.682 L1.2@54.65,48.214 ; L1.2@54.65,47.8 R17.2@61.911,47.8
5V_LCD: C3.2 C4.1 CN2.4 CN2.6 R17.1 | length 14
  Bottom Layer w0.7: v1(150.95,51.775) v1(150.95,50.775) C4.1@149.85,50.775 C3.2@148.4,50.775 ; C3.2@148.4,50.775 148.355,50.73 CN2.4@145.785,50.73 144.6,50.73 143.875,51.455 v1(143.875,52) CN2.6@145.785,52 146.85,52 148.075,50.775 C3.2@148.4,50.775
  other v1: 66.8,49 65,49.05 66.825,50.35 65.025,50.375
5V_VIN: R8.2 U1.1 | length 1.5
  Bottom Layer w0.4: U1.1@47.6,52.964 48.039,52.964
  Bottom Layer w1: 48.039,52.964 R8.2@49.075,52.964
AVDD: J1.8 R16.1 R22.2 | length 32.1
  Bottom Layer w0.4: J1.8@90.29,46.889 90.29,43.985 92.925,41.35 ; 108.575,48.059 109.666,49.15 110.625,49.15 110.9,48.875 R16.1@110.9,48.059 110.009,48.059
  Bottom Layer w1: 92.925,41.35 98.475,41.35 100.584,43.459 R22.2@103.675,43.459 103.675,45.225 106.509,48.059 108.575,48.059 110.009,48.059
CTP_INT: C10.2 CN2.10 J2.3 | length 27.5
  Bottom Layer w0.3: J2.3@144.25,39.235 144.25,41.05 144.358,41.158 C10.2@144.358,42.01 ; C10.2@144.375,42.01 C10.2@144.358,42.01 ; CN2.10@145.785,54.54 150.71,54.54 152.3,52.95 152.3,49.35 150.05,47.1 145.2,47.1 143.8,45.7 143.8,44.95 143.805,44.945 143.805,42.563 C10.2@144.358,42.01
CTP_RST: C13.2 CN2.9 R1.1 | length 22
  Top Layer w0.3: v1(136.85,46.15) v1(142.65,46.15)
  Bottom Layer w0.3: v1(136.85,46.15) 136.85,51.336 139.35,53.836 R1.1@139.35,54.525 141.7,54.525 CN2.9@141.715,54.54 ; v1(142.65,46.15) 142.65,42.543 143.208,41.985 C13.2@143.225,41.985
